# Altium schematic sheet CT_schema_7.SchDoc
size 372 x 245 mm
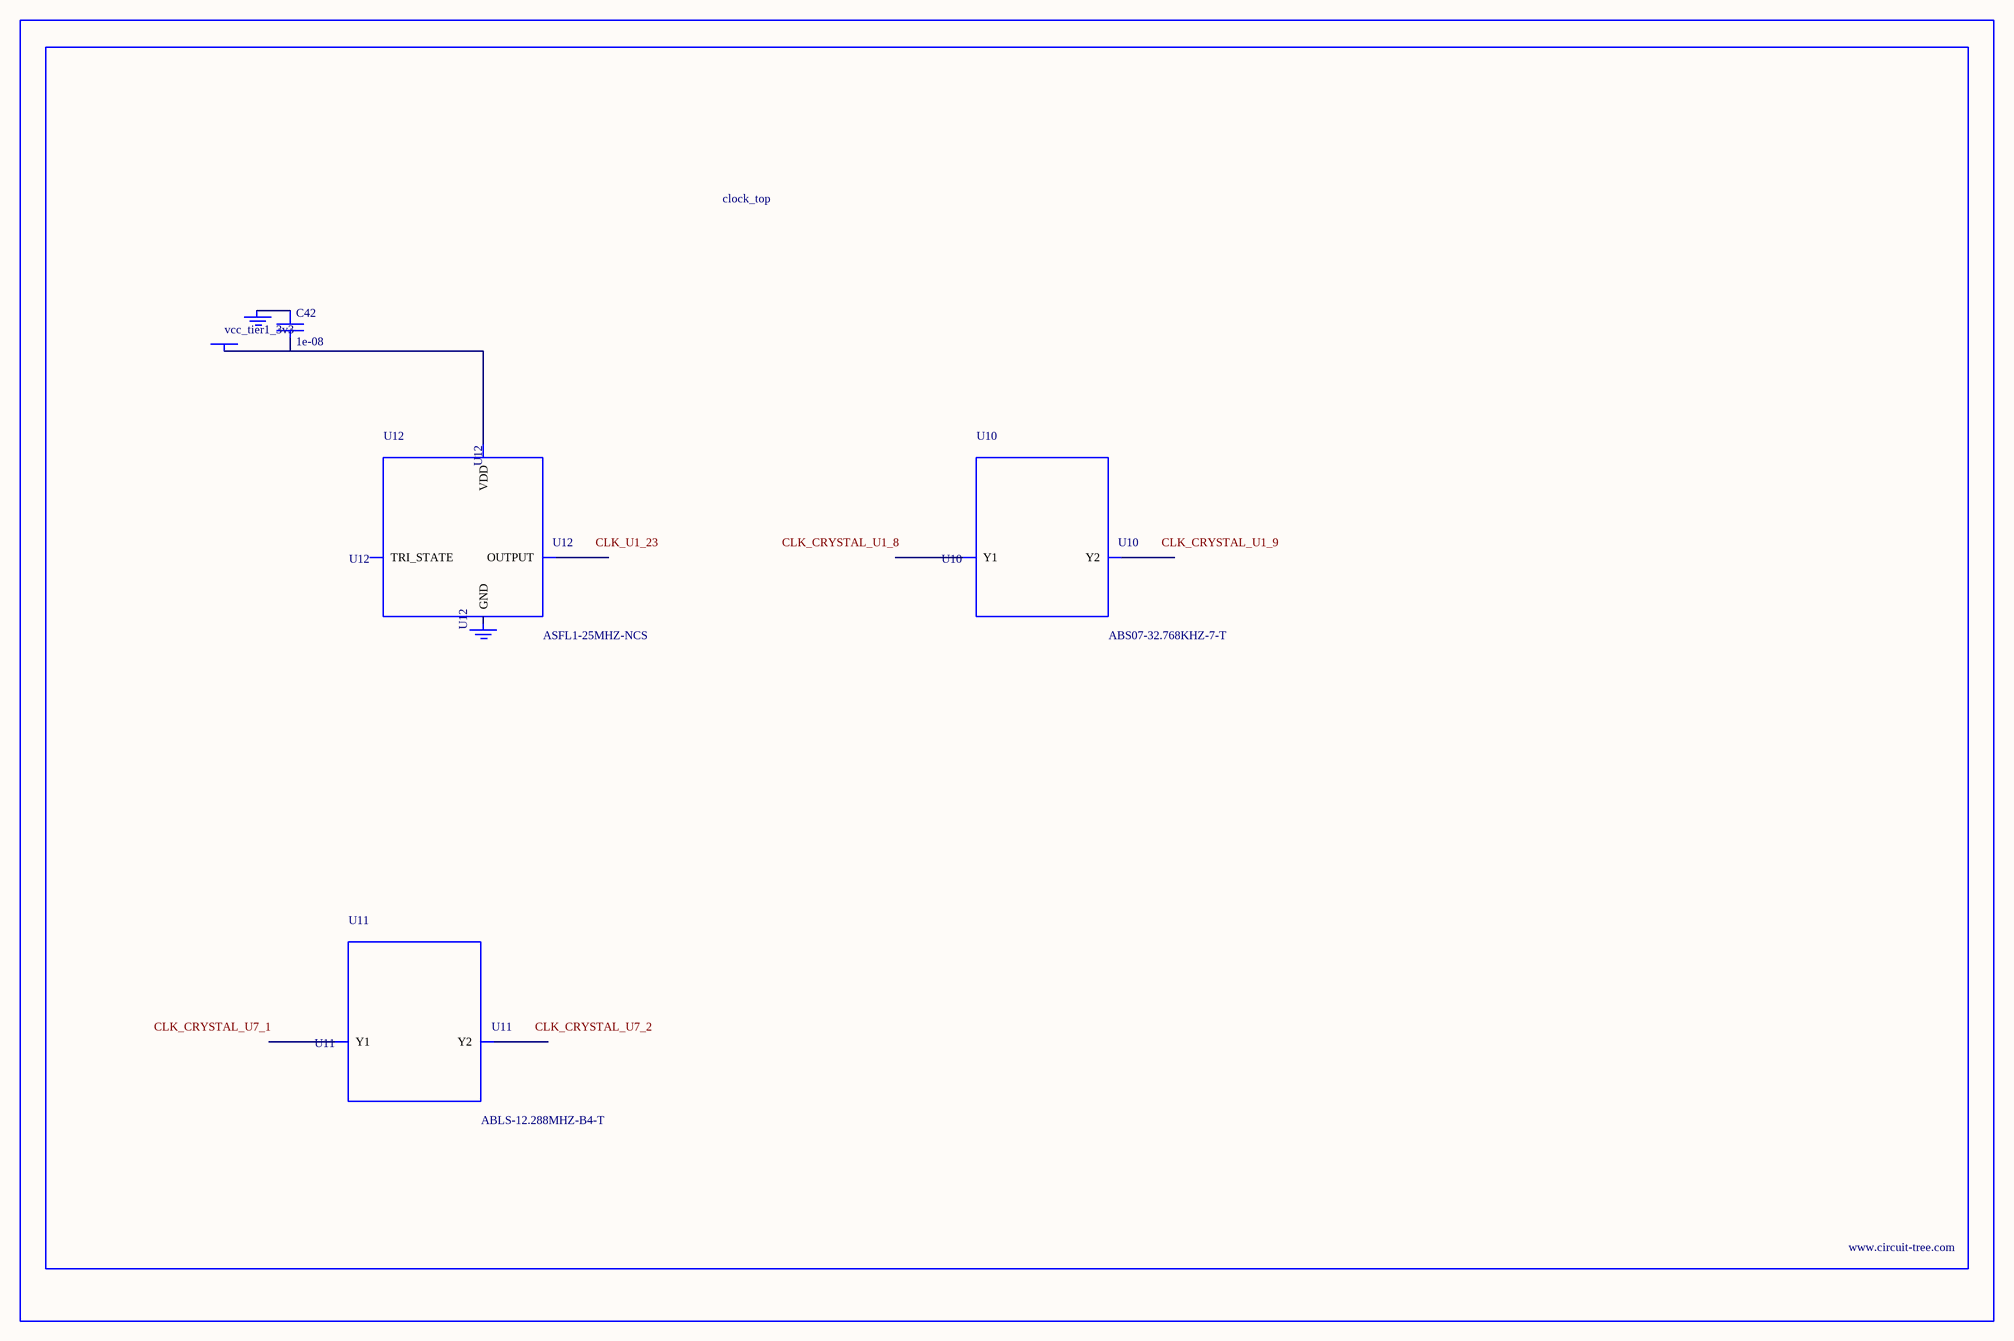
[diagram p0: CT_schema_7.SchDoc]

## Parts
BORDER6  (no value)
C42  1e-08  [C0402]
GND_INSTANCE_6_0  (no value)
GND_INSTANCE_6_1  (no value)
POWER_INSTANCE_6_0  vcc_tier1_3v3
U10  ABS07-32.768KHZ-7-T  [ABS07-32.768KHZ-7-T]
U11  ABLS-12.288MHZ-B4-T  [ABLS-12.288MHZ-B4-T]
U12  ASFL1-25MHZ-NCS  [ASFL1]

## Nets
NetC42_1: C42.1 GND_INSTANCE_6_0.0(GND)
NetC42_2: C42.2 POWER_INSTANCE_6_0.0(PWR) U12.4(VDD)

Not connected (* = marked no-connect by the designer): GND_INSTANCE_6_1 0(GND); U10 1(Y1) 2(Y2); U11 1(Y1) 2(Y2); U12 1(TRI_STATE) 2(GND) 3(OUTPUT)

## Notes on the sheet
- Labels drawn without touching a wire or pin: CLK_CRYSTAL_U1_8, CLK_CRYSTAL_U1_9, CLK_CRYSTAL_U7_1, CLK_CRYSTAL_U7_2, CLK_U1_23

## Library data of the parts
BORDER6 = BORDER_PAGE6
C42 = C0402C103K3RAC
GND_INSTANCE_6_0 GND_INSTANCE_6_1 = GND
POWER_INSTANCE_6_0 = PWR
